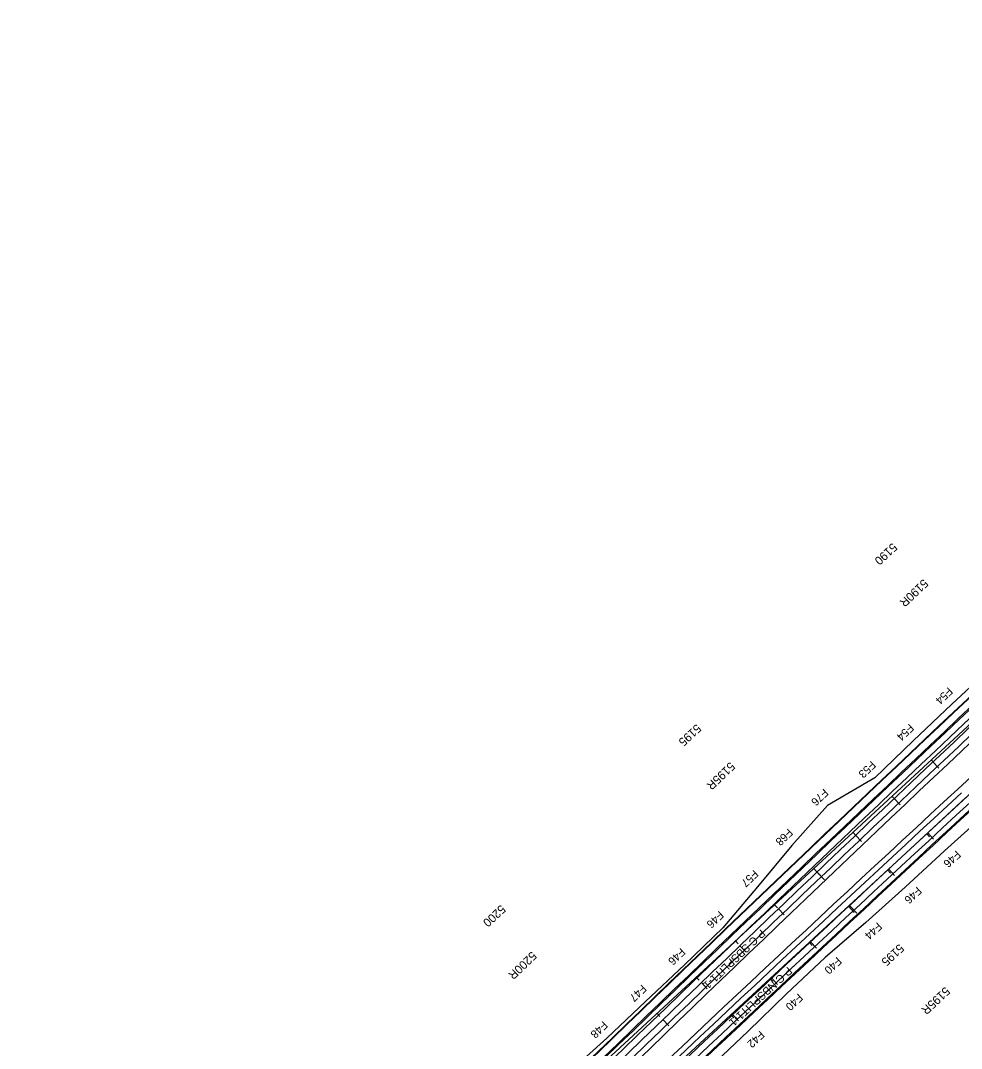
# Model space of a CAD drawing. Extents: x 2160877 to 2175861, y 601747 to 617724.
# Drawn here: x 2168998 to 2170763, y 611848 to 613775 of the extents above; entities that cross this region are included whole.
import ezdxf

# ---------------------------------------------------------------- set-up
doc = ezdxf.new("R2010")
doc.units = 0
for name, color, linetype in [('RD_HC_Cl', 7, 'Continuous'), ('RD_HC_CL_Rel', 7, 'Continuous'), ('RD_HC_Data_Rel', 7, 'Continuous'), ('RD_HC_Data_Tic', 7, 'Continuous'), ('RD_HC_Data_Tic_Rel', 7, 'Continuous'), ('RD_HC_TX_Rel_Sta50', 7, 'Continuous'), ('RD_HC_TX_StaOther', 7, 'Continuous'), ('RD_PD_CstnLmt', 7, 'Continuous'), ('RD_PD_CstnLmt_TX', 7, 'Continuous'), ('RD_PD_Final_LnLine', 7, 'Continuous'), ('RD_PD_Final_TrvlWay', 7, 'Continuous'), ('RD_PD_GR', 7, 'Continuous'), ('RD_PD_MedBWall', 7, 'Continuous')]:
    doc.layers.add(name, color=color, linetype=linetype)

msp = doc.modelspace()

# ---------------------------------------------------------------- linework, layer by layer
at = {"layer": 'RD_HC_Cl'}
for p, q in [((2172207.3, 613775.1), (2163672.2, 605893.8)), ((2172272.5, 613704.6), (2163737.4, 605823.3))]:
    msp.add_line(p, q, dxfattribs=at)
at = {"layer": 'RD_HC_CL_Rel'}
for centre, radius in [((2222221.5, 557873.6), 75000), ((2219616.9, 559421.3), 72000)]:
    msp.add_arc(centre, radius, 132.719474, 134.517591, dxfattribs=at)
at = {"layer": 'RD_HC_Data_Tic'}
for p, q in [((2170706.5, 612389.3), (2170711.9, 612383.4)), ((2170633, 612321.4), (2170638.5, 612315.6)), ((2170559.6, 612253.6), (2170565, 612247.7)), ((2170698.2, 612250.9), (2170703.6, 612245)), ((2170486.1, 612185.8), (2170497, 612174)), ((2170624.7, 612183.1), (2170630.1, 612177.2)), ((2170412.6, 612117.9), (2170418.1, 612112)), ((2170551.2, 612115.2), (2170562.1, 612103.5)), ((2170339.2, 612050.1), (2170344.6, 612044.2)), ((2170477.8, 612047.4), (2170483.2, 612041.5)), ((2170265.7, 611982.2), (2170271.1, 611976.4)), ((2170404.3, 611979.6), (2170409.7, 611973.7)), ((2170192.2, 611914.4), (2170197.7, 611908.5)), ((2170330.8, 611911.7), (2170336.3, 611905.8))]:
    msp.add_line(p, q, dxfattribs=at)
at = {"layer": 'RD_HC_Data_Tic_Rel'}
for p, q in [((2170709.9, 612385.6), (2170720.9, 612374)), ((2170637.3, 612316.9), (2170648.3, 612305.3)), ((2170700.1, 612252.6), (2170711, 612240.9)), ((2170564.7, 612248.1), (2170575.7, 612236.5)), ((2170492.3, 612179.2), (2170506.1, 612164.7)), ((2170626.8, 612184.6), (2170637.7, 612172.9)), ((2170419.9, 612110.1), (2170431, 612098.6)), ((2170553.6, 612116.5), (2170567.2, 612101.9)), ((2170347.6, 612041), (2170358.7, 612029.5)), ((2170480.4, 612048.4), (2170491.3, 612036.7)), ((2170275.5, 611971.8), (2170286.5, 611960.3)), ((2170407.4, 611980.1), (2170418.3, 611968.4)), ((2170334.4, 611911.7), (2170345.4, 611900)), ((2170203.4, 611902.5), (2170214.5, 611891))]:
    msp.add_line(p, q, dxfattribs=at)
at = {"layer": 'RD_PD_CstnLmt'}
for p, q in [((2170818.5, 612562.2), (2170745.3, 612493.8)), ((2170745.3, 612493.8), (2170672.5, 612425.2)), ((2170672.5, 612425.2), (2170600.7, 612355.5)), ((2170600.7, 612355.5), (2170512, 612303.6)), ((2170512, 612303.6), (2170445.1, 612228.7)), ((2170805.7, 612285.7), (2170731.3, 612218.9)), ((2170445.1, 612228.7), (2170380.6, 612151.3)), ((2170731.3, 612218.9), (2170658, 612151)), ((2170380.6, 612151.3), (2170315.7, 612074.3)), ((2170658, 612151), (2170583.7, 612084.2)), ((2170583.7, 612084.2), (2170507.8, 612019)), ((2170315.7, 612074.3), (2170243.6, 612005)), ((2170243.6, 612005), (2170170.9, 611936.2)), ((2170507.8, 612019), (2170434.9, 611950.6)), ((2170434.9, 611950.6), (2170363.2, 611881)), ((2170170.9, 611936.2), (2170097.9, 611867.7)), ((2170097.9, 611867.7), (2170023.5, 611800.8)), ((2170363.2, 611881), (2170290.7, 611812.3))]:
    msp.add_line(p, q, dxfattribs=at)
at = {"layer": 'RD_PD_Final_LnLine'}
for centre, radius in [((2222221.5, 557873.6), 75012), ((2222221.5, 557873.6), 74988), ((2219616.9, 559421.3), 72012), ((2219616.9, 559421.3), 71988)]:
    msp.add_arc(centre, radius, 132.719474, 134.517591, dxfattribs=at)
at = {"layer": 'RD_PD_Final_TrvlWay'}
msp.add_line((2172257.5, 613720.8), (2170756.5, 612334.7), dxfattribs=at)
for centre, radius in [((2222220.1, 557875.1), 75024.3), ((2222220.1, 557875.1), 75022), ((2222221.5, 557873.6), 74978), ((2219616.9, 559421.3), 72022), ((2219616.9, 559421.3), 71978)]:
    msp.add_arc(centre, radius, 132.719474, 134.517591, dxfattribs=at)
at = {"layer": 'RD_PD_GR'}
msp.add_arc((2219616.9, 559421.3), 71976, 132.719474, 134.517591, dxfattribs=at)
at = {"layer": 'RD_PD_MedBWall'}
for radius in [75039.3, 75038.3]:
    msp.add_arc((2222220.1, 557875.1), radius, 132.719474, 134.517591, dxfattribs=at)

# ---------------------------------------------------------------- texts
at = {"layer": 'RD_HC_Data_Rel'}
for s, rotation, p in [('P C SBSPLIT1-1', 223.5528, (2170386.8, 612072.9)), ('P C NBSPLIT1-1', 222.7536, (2170437.4, 612002.5))]:
    msp.add_text(s, height=15, rotation=rotation, dxfattribs=at).set_placement(p)
at = {"layer": 'RD_HC_TX_Rel_Sta50'}
for s, rotation, p in [('5190R', 223.2262, (2170691.9, 612729.3)), ('5195R', 223.6082, (2170329.4, 612386.5)), ('5200R', 223.9901, (2169957.2, 612031.3)), ('5195R', 222.9559, (2170732.8, 611965))]:
    msp.add_text(s, height=16, rotation=rotation, dxfattribs=at).set_placement(p)
at = {"layer": 'RD_HC_TX_StaOther'}
for s, p in [('5190', (2170633.9, 612797.1)), ('5195', (2170266.2, 612457.5)), ('5200', (2169899.3, 612118.7)), ('5195', (2170646.7, 612045.5))]:
    msp.add_text(s, height=16, rotation=222.7195, dxfattribs=at).set_placement(p)
at = {"layer": 'RD_PD_CstnLmt_TX'}
for s, rotation, p in [('F54', 223.3026, (2170738.4, 612526.6)), ('F54', 223.379, (2170665.6, 612458)), ('F53', 223.4554, (2170594, 612388.5)), ('F76', 223.5318, (2170505.1, 612336.4)), ('F68', 223.6082, (2170438.3, 612261.7)), ('F46', 222.7968, (2170753.6, 612220.5)), ('F57', 223.6845, (2170373.7, 612184.2)), ('F46', 222.8764, (2170680.2, 612152.7)), ('F46', 223.7609, (2170308.8, 612107.2)), ('F44', 222.9559, (2170605.8, 612085.8)), ('F46', 223.8373, (2170236.7, 612037.9)), ('F40', 223.0355, (2170530.1, 612020.8)), ('F47', 223.9137, (2170163.9, 611969.2)), ('F40', 223.1151, (2170457.3, 611952.4)), ('F48', 223.9901, (2170091, 611900.8)), ('F42', 223.1947, (2170385.3, 611882.7))]:
    msp.add_text(s, height=15, rotation=rotation, dxfattribs=at).set_placement(p)

doc.saveas('drawing.dxf')
